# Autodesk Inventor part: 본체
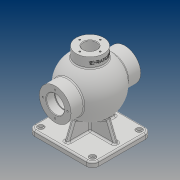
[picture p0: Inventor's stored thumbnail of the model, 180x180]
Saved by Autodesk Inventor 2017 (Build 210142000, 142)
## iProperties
Part Number: 본체
Material: 일반
Document SubType Name: Modeling
Designer: 13
Density: 1 g/cm^3
Appearance: 기본값
Author: 13
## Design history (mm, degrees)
sketch "스케치1"
  geometry: L1 (-68, 0)-(68, 0); L2 (39.278, 17.5)-(68, 17.5); L3 (-68, 17.5)-(-68, 31); L4 (-68, 31)-(-42.988, 31); L5 (68, 17.5)-(68, 31); L6 (68, 31)-(42.988, 31); L7 (-39.278, 17.5)-(-50.25, 17.5); L8 (-50.25, 17.5)-(-50.25, 18.5); L9 (-50.25, 18.5)-(-52, 18.5); L10 (-52, 18.5)-(-52, 17.5); L11 (-52, 17.5)-(-68, 17.5); A1 r 43 centre (0, 0) between (39.278, 17.5) and (-39.278, 17.5); A2 r 53 centre (0, 0) between (42.988, 31) and (-42.988, 31); 2 further points
  constraints: 22 end point, 7 horizontal, 4 point on circle, 4 vertical, 3 coincident, 3 point on line, 2 centre point, 1 midpoint
  dimensions: "d0" = 136 distance of L1.start L1.end; "d1" = 43 radius of A1; "d2" = 53 radius of A2; "d4" = 62 diameter of L4 L1; "d5" = 35 diameter of L2 L1; "d6" = 62 diameter of L6 L1; "d92" = 35 diameter of L11 L1; "d93" = 37 diameter of L9 L1; "d94" = 1.75 distance between parallel lines of L10 L8; "d95" = 16 distance between parallel lines of L3 L10
revolve "회전1" sketch "스케치1" stored, may be unused: angle "d7" = 90 deg
node "작업 평면1"
sketch "스케치4"
  geometry: L1 (-62.5, 57.5)-(62.5, 57.5); L2 (62.5, 57.5)-(62.5, -57.5); L3 (62.5, -57.5)-(-62.5, -57.5); L4 (-62.5, -57.5)-(-62.5, 57.5); L5 (-62.5, 57.5)-(62.5, -57.5); L6 (62.5, 57.5)-(-62.5, -57.5); 1 further point
  constraints: 12 end point, 2 midpoint, 2 parallel, 1 horizontal, 1 perpendicular
  dimensions: "d31" = 125 distance of L1.start L1.end; "d32" = 115 distance of L1.end L2.end
extrude "돌출1" join sketch "스케치4" distance "d33" = 10; taper "d34" = 0 deg
fillet "모깎기1" dims "d53" = 12
hole "구멍3" diameter "d56" = 8; stored, may be unused: countersink angle "d60" = 90 deg, drill point angle "d62" = 0 deg; dims "d54" = 10, "d55" = 10, "d57" = 8, "d58" = 12, "d59" = 3, "d61" = 10
node "작업 평면2"
sketch "스케치9"
  geometry: C1 r 27 at (0, 0); 1 further point
  constraints: 1 centre point, 1 coincident
  dimensions: "d70" = 54 diameter of C1
extrude "돌출5" join sketch "스케치9" stored distance "d71" = 8; taper "d72" = 0 deg
sketch "스케치11"
  geometry: C1 r 13 at (0, 0); 1 further point
  constraints: 1 centre point, 1 coincident
  dimensions: "d73" = 26 diameter of C1
extrude "돌출6" cut sketch "스케치11" distance "d74" = 40; taper "d75" = 0 deg
sketch "스케치12"
  geometry: 2 further points
  constraints: 1 vertical alignment
  dimensions: "d76" = 20 distance of point (0, 0) point (0, 20)
hole "구멍4" sketch "스케치12" at (0, 20) diameter "d77" = 3.242; stored, may be unused: countersink angle "d81" = 90 deg, drill point angle "d83" = 0 deg; dims "d78" = 9, "d79" = 12, "d80" = 3, "d82" = 11
fillet "모깎기2" dims "d87" = 3
fillet "모깎기3" dims "d88" = 3
fillet "모깎기4" dims "d89" = 3
sketch "스케치13"
  geometry: 2 further points
  constraints: 1 vertical alignment
  dimensions: "d96" = 24 distance of point (0, 0) point (0, 24)
hole "구멍5" sketch "스케치13" at (0, 24) diameter "d97" = 3.242; stored, may be unused: countersink angle "d101" = 90 deg, drill point angle "d103" = 0 deg; dims "d98" = 16, "d99" = 12, "d100" = 3, "d102" = 19
sketch "스케치14"
  geometry: 2 further points
  constraints: 1 vertical alignment
  dimensions: "d107" = 22.5 distance of point (0, 0) point (0, -22.5)
hole "구멍6" sketch "스케치14" at (0, -22.5) diameter "d108" = 3.242; stored, may be unused: countersink angle "d112" = 90 deg, drill point angle "d114" = 0 deg; dims "d109" = 12, "d110" = 12, "d111" = 3, "d113" = 15
chamfer "모따기1" distance "d118" = 1; stored, may be unused: second distance "d119" = 2, angle "d120" = 45 deg
sketch "스케치29"
  geometry: L1 (52.5, -75)-(35.597, -33.164); L2 (62.5, -85)-(62.5, -78) reference; L3 (50.5, -75)-(-50.5, -75) reference; L4 (52.5, -75)-(0, -75); L5 (0, -75)-(0, -48.652); A1 r 48.652 centre (0, 0) between (0, -48.652) and (35.597, -33.164); 1 further point
  constraints: 6 end point, 2 point on circle, 1 centre point, 1 coincident, 1 midpoint, 1 point on line, 1 vertical
  dimensions: "d158" = 10 distance from line of L2 L1.start; "d159" = 22 deg angle of L2 L1; "d161" = 97.30374 diameter of A1
extrude "돌출9" join sketch "스케치29" stored distance "d162" = 8; taper "d163" = 0 deg
sketch "스케치30"
  geometry: L1 (-45.5, -75)-(45.5, -75) reference; L2 (-32.761, -38.519)-(-47.5, -75); L3 (-57.5, -85)-(-57.5, -78) reference; L4 (-47.5, -75)-(0, -75); L5 (0, -75)-(0, -50.566); A1 r 50.566 centre (0, 0) between (-32.761, -38.519) and (0, -50.566); 1 further point
  constraints: 6 end point, 2 point on circle, 1 centre point, 1 coincident, 1 midpoint, 1 point on line, 1 vertical
  dimensions: "d164" = 10 distance from line of L3 L2.end; "d165" = 22 deg angle of L3 L2; "d166" = 101.13283 diameter of A1
extrude "돌출10" join sketch "스케치30" stored distance "d167" = 8; taper "d168" = 0 deg
fillet "모깎기8" dims "d169" = 3
fillet "모깎기9" dims "d170" = 3
node "작업 평면4"
sketch "스케치32"
  geometry: L1 (-27, 65)-(-27, 47.286) reference; L2 (27, 65)-(-27, 65) reference; 2 further points
  constraints: 1 other
  dimensions: "d172" = 27 distance from line of L1 point (0, 55); "d173" = 10 distance from line of L2 point (0, 55)
feature "엠보싱1" sketch "스케치32" dims "d0" = 136, "d1" = 43, "d2" = 53, "d4" = 62, "d5" = 35, "d6" = 62, "d92" = 35, "d93" = 37, "d94" = 1.75, "d95" = 16, "d174" = 0.5, "d175" = 0
node "솔리드1"
pattern_linear "직사각형 패턴1" dims "d65" = 101, "d68" = 91
pattern_circular "원형 패턴3" dims angle "d85" = 360 deg
pattern_circular "원형 패턴4" dims angle "d105" = 360 deg
pattern_circular "원형 패턴5" dims angle "d116" = 360 deg
mirror "미러3"
mirror "미러4"
other parameters: "d30" = -85, "d171" = 65
